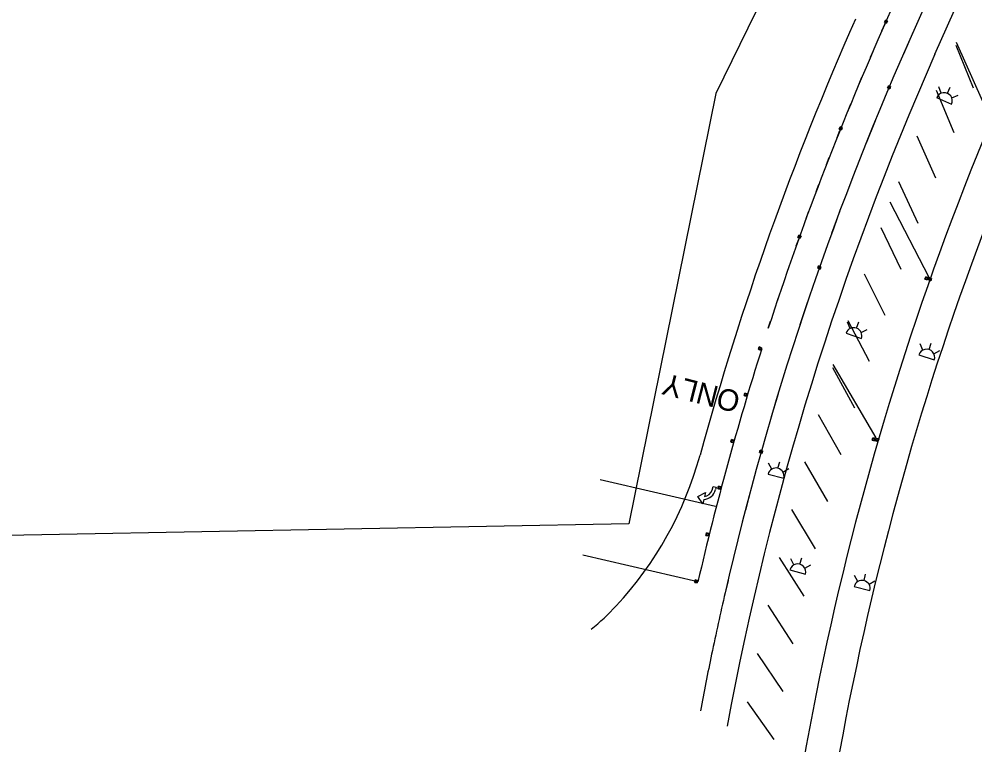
# Model space of a CAD drawing. Extents: x 2471014 to 2497726, y 6959577 to 6980268.
# Drawn here: x 2487942.2 to 2488337.8, y 6964058.7 to 6964359.1 of the extents above; entities that cross this region are included whole.
import ezdxf

# ---------------------------------------------------------------- set-up
doc = ezdxf.new("R2010")
doc.units = 0
for name, color, linetype in [('1', 7, 'Continuous'), ('13', 7, 'Continuous'), ('18', 7, 'Continuous'), ('23', 7, 'Continuous'), ('25', 7, 'Continuous'), ('C-ANNO-NOTE', 7, 'Continuous'), ('G-GRID-MAJR', 7, 'Continuous'), ('Level 30', 7, 'Continuous'), ('p_structure fence', 7, 'Continuous'), ('p_structure wall', 7, 'Continuous'), ('PMK_Del_D-SY_SZ_TYC_CTB', 7, 'Continuous'), ('PMK_Pav_Marker_TY I C', 7, 'Continuous'), ('S-BRDG-DECK', 7, 'Continuous'), ('V7_50', 7, 'Continuous')]:
    doc.layers.add(name, color=color, linetype=linetype)

msp = doc.modelspace()

# ---------------------------------------------------------------- linework, layer by layer
at = {"layer": '1'}
for p, q in [((2488312.25, 6964353.78), (2488308.21, 6964344.63)), ((2488296.51, 6964317.01), (2488292.76, 6964307.74)), ((2488281.93, 6964279.76), (2488278.47, 6964270.38)), ((2488268.54, 6964242.07), (2488265.38, 6964232.58)), ((2488256.35, 6964203.98), (2488253.49, 6964194.39)), ((2488245.37, 6964165.51), (2488242.82, 6964155.85)), ((2488235.62, 6964126.72), (2488234.43, 6964121.64))]:
    msp.add_line(p, q, dxfattribs=at)
at = {"layer": '13'}
msp.add_line((2488321.27, 6964344.52), (2488442.52, 6964618.47), dxfattribs=at)
for centre, radius, start, end in [((2489466.16, 6963837.82), 1252, 156.12666, 169.47895), ((2489494.86, 6963836.39), 1232.74, 155.64615, 177.1468)]:
    msp.add_arc(centre, radius, start, end, dxfattribs=at)
at = {"layer": '18'}
for centre, radius, start, end in [((2489466.16, 6963837.82), 1288, 156.12666, 164.66113), ((2489494.86, 6963836.39), 1246.74, 155.64615, 177.1468), ((2490212.3, 6963600.12), 1910, 158.95644, 170.95139), ((2488079.38, 6964218.21), 150, 317.1511, 344.6611), ((2489466.16, 6963837.82), 1264, 167.02427, 168.20604), ((2488116.77, 6964183.53), 99, 308.9318, 317.1511), ((2489436.79, 6963843.95), 1234, 168.20604, 169.31709)]:
    msp.add_arc(centre, radius, start, end, dxfattribs=at)
at = {"layer": '23'}
for p, q in [((2488301.61, 6964330.59), (2488302, 6964331.52)), ((2488301.83, 6964330.68), (2488301.61, 6964330.59)), ((2488301.61, 6964330.59), (2488302.54, 6964330.2)), ((2488302.33, 6964330.47), (2488301.83, 6964330.68)), ((2488302.69, 6964331.23), (2488302, 6964331.52)), ((2488302, 6964331.52), (2488302.1, 6964331.3)), ((2488302.1, 6964331.3), (2488302.72, 6964331.04)), ((2488302.46, 6964330.41), (2488302.33, 6964330.47)), ((2488302.54, 6964330.2), (2488302.46, 6964330.41)), ((2488302.93, 6964331.13), (2488302.54, 6964330.2)), ((2488302.93, 6964331.13), (2488302.69, 6964331.23)), ((2488302.72, 6964331.04), (2488302.93, 6964331.13)), ((2488272.77, 6964255.95), (2488273.11, 6964256.9)), ((2488272.99, 6964256.05), (2488272.77, 6964255.95)), ((2488272.77, 6964255.95), (2488273.73, 6964255.61)), ((2488273.5, 6964255.87), (2488272.99, 6964256.05)), ((2488273.81, 6964256.66), (2488273.11, 6964256.9)), ((2488273.11, 6964256.9), (2488273.22, 6964256.69)), ((2488273.22, 6964256.69), (2488273.86, 6964256.46)), ((2488273.63, 6964255.82), (2488273.5, 6964255.87)), ((2488273.73, 6964255.61), (2488273.63, 6964255.82)), ((2488274.06, 6964256.57), (2488273.73, 6964255.61)), ((2488274.06, 6964256.57), (2488273.81, 6964256.66)), ((2488273.86, 6964256.46), (2488274.06, 6964256.57)), ((2488317.08, 6964251.48), (2488317.42, 6964252.43)), ((2488317.3, 6964251.58), (2488317.08, 6964251.48)), ((2488317.08, 6964251.48), (2488318.03, 6964251.13)), ((2488317.81, 6964251.4), (2488317.3, 6964251.58)), ((2488318.12, 6964252.18), (2488317.42, 6964252.43)), ((2488317.42, 6964252.43), (2488317.53, 6964252.21)), ((2488317.53, 6964252.21), (2488318.17, 6964251.98)), ((2488317.94, 6964251.35), (2488317.81, 6964251.4)), ((2488318.03, 6964251.13), (2488317.94, 6964251.35)), ((2488318.37, 6964252.09), (2488318.03, 6964251.13)), ((2488318.37, 6964252.09), (2488318.12, 6964252.18)), ((2488318.17, 6964251.98), (2488318.37, 6964252.09)), ((2488318.55, 6964251.14), (2488318.9, 6964252.09)), ((2488318.78, 6964251.24), (2488318.55, 6964251.14)), ((2488318.55, 6964251.14), (2488319.5, 6964250.8)), ((2488319.28, 6964251.06), (2488318.78, 6964251.24)), ((2488319.59, 6964251.84), (2488318.9, 6964252.09)), ((2488318.9, 6964252.09), (2488319, 6964251.88)), ((2488319, 6964251.88), (2488319.64, 6964251.65)), ((2488319.41, 6964251.01), (2488319.28, 6964251.06)), ((2488319.5, 6964250.8), (2488319.41, 6964251.01)), ((2488319.85, 6964251.75), (2488319.5, 6964250.8)), ((2488319.85, 6964251.75), (2488319.59, 6964251.84)), ((2488319.64, 6964251.65), (2488319.85, 6964251.75)), ((2488248.18, 6964222.41), (2488248.49, 6964223.38)), ((2488248.39, 6964222.52), (2488248.18, 6964222.41)), ((2488248.18, 6964222.41), (2488248.44, 6964222.33)), ((2488249.03, 6964222.31), (2488248.39, 6964222.52)), ((2488248.44, 6964222.33), (2488249.15, 6964222.1)), ((2488249.46, 6964223.07), (2488248.49, 6964223.38)), ((2488248.49, 6964223.38), (2488248.59, 6964223.16)), ((2488248.59, 6964223.16), (2488248.73, 6964223.12)), ((2488248.73, 6964223.12), (2488249.24, 6964222.96)), ((2488249.15, 6964222.1), (2488249.03, 6964222.31)), ((2488249.46, 6964223.07), (2488249.15, 6964222.1)), ((2488249.24, 6964222.96), (2488249.46, 6964223.07)), ((2488242.31, 6964203.28), (2488242.6, 6964204.25)), ((2488242.51, 6964203.4), (2488242.31, 6964203.28)), ((2488242.31, 6964203.28), (2488242.57, 6964203.2)), ((2488243.16, 6964203.2), (2488242.51, 6964203.4)), ((2488242.57, 6964203.2), (2488243.28, 6964202.99)), ((2488243.57, 6964203.96), (2488242.6, 6964204.25)), ((2488242.6, 6964204.25), (2488242.7, 6964204.05)), ((2488242.7, 6964204.05), (2488242.84, 6964204)), ((2488242.84, 6964204), (2488243.35, 6964203.85)), ((2488243.28, 6964202.99), (2488243.16, 6964203.2)), ((2488243.57, 6964203.96), (2488243.28, 6964202.99)), ((2488243.35, 6964203.85), (2488243.57, 6964203.96)), ((2488295.23, 6964184.85), (2488295.52, 6964185.82)), ((2488296.23, 6964185.61), (2488295.52, 6964185.82)), ((2488295.52, 6964185.82), (2488295.64, 6964185.61)), ((2488236.74, 6964184.07), (2488237.01, 6964185.04)), ((2488236.93, 6964184.18), (2488236.74, 6964184.07)), ((2488236.74, 6964184.07), (2488236.99, 6964183.99)), ((2488237.59, 6964184), (2488236.93, 6964184.18)), ((2488236.99, 6964183.99), (2488237.71, 6964183.79)), ((2488237.99, 6964184.77), (2488237.01, 6964185.04)), ((2488237.01, 6964185.04), (2488237.12, 6964184.84)), ((2488237.12, 6964184.84), (2488237.25, 6964184.8)), ((2488237.25, 6964184.8), (2488237.77, 6964184.65)), ((2488237.71, 6964183.79), (2488237.59, 6964184)), ((2488237.99, 6964184.77), (2488237.71, 6964183.79)), ((2488237.77, 6964184.65), (2488237.99, 6964184.77)), ((2488295.45, 6964184.96), (2488295.23, 6964184.85)), ((2488295.23, 6964184.85), (2488296.2, 6964184.56)), ((2488295.96, 6964184.81), (2488295.45, 6964184.96)), ((2488295.64, 6964185.61), (2488296.29, 6964185.42)), ((2488296.1, 6964184.77), (2488295.96, 6964184.81)), ((2488296.2, 6964184.56), (2488296.1, 6964184.77)), ((2488296.49, 6964185.53), (2488296.2, 6964184.56)), ((2488296.49, 6964185.53), (2488296.23, 6964185.61)), ((2488296.29, 6964185.42), (2488296.49, 6964185.53)), ((2488296.71, 6964184.56), (2488297, 6964185.53)), ((2488296.93, 6964184.67), (2488296.71, 6964184.56)), ((2488296.71, 6964184.56), (2488297.68, 6964184.27)), ((2488297.44, 6964184.52), (2488296.93, 6964184.67)), ((2488297.71, 6964185.32), (2488297, 6964185.53)), ((2488297, 6964185.53), (2488297.12, 6964185.32)), ((2488297.12, 6964185.32), (2488297.77, 6964185.13)), ((2488297.58, 6964184.48), (2488297.44, 6964184.52)), ((2488297.68, 6964184.27), (2488297.58, 6964184.48)), ((2488297.97, 6964185.24), (2488297.68, 6964184.27)), ((2488297.97, 6964185.24), (2488297.71, 6964185.32)), ((2488297.77, 6964185.13), (2488297.97, 6964185.24)), ((2488248.71, 6964179.63), (2488248.99, 6964180.61)), ((2488248.93, 6964179.75), (2488248.71, 6964179.63)), ((2488248.71, 6964179.63), (2488249.69, 6964179.36)), ((2488249.44, 6964179.6), (2488248.93, 6964179.75)), ((2488249.7, 6964180.4), (2488248.99, 6964180.61)), ((2488248.99, 6964180.61), (2488249.11, 6964180.4)), ((2488249.11, 6964180.4), (2488249.76, 6964180.21)), ((2488249.58, 6964179.56), (2488249.44, 6964179.6)), ((2488249.69, 6964179.36), (2488249.58, 6964179.56)), ((2488249.96, 6964180.33), (2488249.69, 6964179.36)), ((2488249.96, 6964180.33), (2488249.7, 6964180.4)), ((2488249.76, 6964180.21), (2488249.96, 6964180.33)), ((2488231.46, 6964164.77), (2488231.72, 6964165.75)), ((2488231.66, 6964164.89), (2488231.46, 6964164.77)), ((2488231.46, 6964164.77), (2488231.72, 6964164.7)), ((2488232.31, 6964164.71), (2488231.66, 6964164.89)), ((2488232.7, 6964165.49), (2488231.72, 6964165.75)), ((2488231.72, 6964165.75), (2488231.83, 6964165.54)), ((2488231.72, 6964164.7), (2488232.44, 6964164.51)), ((2488231.83, 6964165.54), (2488231.97, 6964165.51)), ((2488231.97, 6964165.51), (2488232.49, 6964165.37)), ((2488232.44, 6964164.51), (2488232.31, 6964164.71)), ((2488232.7, 6964165.49), (2488232.44, 6964164.51)), ((2488232.49, 6964165.37), (2488232.7, 6964165.49)), ((2488226.49, 6964145.39), (2488226.74, 6964146.37)), ((2488227.72, 6964146.12), (2488226.74, 6964146.37)), ((2488226.74, 6964146.37), (2488226.85, 6964146.17)), ((2488226.85, 6964146.17), (2488226.99, 6964146.13)), ((2488226.69, 6964145.51), (2488226.49, 6964145.39)), ((2488226.49, 6964145.39), (2488226.75, 6964145.32)), ((2488227.35, 6964145.35), (2488226.69, 6964145.51)), ((2488226.75, 6964145.32), (2488227.48, 6964145.14)), ((2488226.99, 6964146.13), (2488227.51, 6964146)), ((2488227.48, 6964145.14), (2488227.35, 6964145.35)), ((2488227.72, 6964146.12), (2488227.48, 6964145.14)), ((2488227.51, 6964146), (2488227.72, 6964146.12)), ((2488221.83, 6964125.93), (2488222.06, 6964126.92)), ((2488223.04, 6964126.69), (2488222.06, 6964126.92)), ((2488222.06, 6964126.92), (2488222.17, 6964126.72)), ((2488222.17, 6964126.72), (2488222.31, 6964126.68)), ((2488222.31, 6964126.68), (2488222.83, 6964126.56)), ((2488223.04, 6964126.69), (2488222.81, 6964125.7)), ((2488222.83, 6964126.56), (2488223.04, 6964126.69)), ((2488222.02, 6964126.06), (2488221.83, 6964125.93)), ((2488221.83, 6964125.93), (2488222.09, 6964125.87)), ((2488222.68, 6964125.9), (2488222.02, 6964126.06)), ((2488222.09, 6964125.87), (2488222.81, 6964125.7)), ((2488222.81, 6964125.7), (2488222.68, 6964125.9))]:
    msp.add_line(p, q, dxfattribs=at)
for points in [[(2488302.72, 6964331.04), (2488302.46, 6964330.41), (2488301.83, 6964330.68), (2488302.1, 6964331.3)], [(2488273.86, 6964256.46), (2488273.63, 6964255.82), (2488272.99, 6964256.05), (2488273.22, 6964256.69)], [(2488318.17, 6964251.98), (2488317.94, 6964251.35), (2488317.3, 6964251.58), (2488317.53, 6964252.21)], [(2488319.64, 6964251.65), (2488319.41, 6964251.01), (2488318.78, 6964251.24), (2488319, 6964251.88)], [(2488248.39, 6964222.52), (2488248.59, 6964223.16), (2488249.24, 6964222.96), (2488249.03, 6964222.31)], [(2488242.51, 6964203.4), (2488242.7, 6964204.05), (2488243.35, 6964203.85), (2488243.16, 6964203.2)], [(2488236.93, 6964184.18), (2488237.12, 6964184.84), (2488237.77, 6964184.65), (2488237.59, 6964184)], [(2488296.29, 6964185.42), (2488296.1, 6964184.77), (2488295.45, 6964184.96), (2488295.64, 6964185.61)], [(2488297.77, 6964185.13), (2488297.58, 6964184.48), (2488296.93, 6964184.67), (2488297.12, 6964185.32)], [(2488249.76, 6964180.21), (2488249.58, 6964179.56), (2488248.93, 6964179.75), (2488249.11, 6964180.4)], [(2488231.66, 6964164.89), (2488231.83, 6964165.54), (2488232.49, 6964165.37), (2488232.31, 6964164.71)], [(2488226.69, 6964145.51), (2488226.85, 6964146.17), (2488227.51, 6964146), (2488227.35, 6964145.35)], [(2488222.02, 6964126.06), (2488222.17, 6964126.72), (2488222.83, 6964126.56), (2488222.68, 6964125.9)]]:
    msp.add_lwpolyline(points, close=True, dxfattribs=at)
at = {"layer": '25'}
for p, q in [((2488299.39, 6964354.39), (2488300.61, 6964357.13)), ((2488294.59, 6964343.39), (2488295.78, 6964346.15)), ((2488289.88, 6964332.35), (2488291.05, 6964335.12)), ((2488285.29, 6964321.27), (2488286.43, 6964324.04)), ((2488280.79, 6964310.14), (2488281.91, 6964312.93)), ((2488276.4, 6964298.97), (2488277.49, 6964301.77)), ((2488272.12, 6964287.76), (2488273.18, 6964290.57)), ((2488267.94, 6964276.52), (2488268.97, 6964279.33)), ((2488263.87, 6964265.23), (2488264.88, 6964268.05)), ((2488259.9, 6964253.9), (2488260.88, 6964256.74)), ((2488256.04, 6964242.54), (2488257, 6964245.38)), ((2488252.29, 6964231.14), (2488253.22, 6964233.99))]:
    msp.add_line(p, q, dxfattribs=at)
msp.add_arc((2489466.16, 6963837.82), 1276, 162.45055, 166.94082, dxfattribs=at)
at = {"layer": 'C-ANNO-NOTE'}
for p, q in [((2488299.33, 6964354.24), (2488420.57, 6964628.19)), ((2488431.55, 6964623.33), (2488310.3, 6964349.38)), ((2488230.39, 6964157.31), (2488182.7, 6964168.38)), ((2488223.16, 6964126.14), (2488175.47, 6964137.2))]:
    msp.add_line(p, q, dxfattribs=at)
for radius, end in [(1276, 162.04643), (1264, 167.02427)]:
    msp.add_arc((2489466.16, 6963837.82), radius, 156.12666, end, dxfattribs=at)
at = {"layer": 'G-GRID-MAJR'}
for p, q in [((2488330.07, 6964349.51), (2488344.35, 6964317.35)), ((2488302.6, 6964283.52), (2488318.7, 6964252.23)), ((2488278.95, 6964216.06), (2488296.82, 6964185.74))]:
    msp.add_line(p, q, dxfattribs=at)
at = {"layer": 'Level 30'}
for p, q in [((2488323.83, 6964328.42), (2488322.91, 6964331.08)), ((2488326.41, 6964328.37), (2488327.54, 6964330.95)), ((2488321.97, 6964326.63), (2488328.15, 6964323.93)), ((2488328.2, 6964326.51), (2488330.81, 6964327.57)), ((2488286.22, 6964231.03), (2488285.13, 6964233.62)), ((2488288.8, 6964231.15), (2488289.76, 6964233.79)), ((2488290.71, 6964229.41), (2488293.24, 6964230.64)), ((2488284.48, 6964229.12), (2488290.83, 6964226.83)), ((2488262.82, 6964133.17), (2488261.56, 6964135.69)), ((2488265.39, 6964133.45), (2488266.18, 6964136.15)), ((2488261.2, 6964131.16), (2488267.68, 6964129.26)), ((2488267.4, 6964131.83), (2488269.85, 6964133.21))]:
    msp.add_line(p, q, dxfattribs=at)
for centre, start, end in [((2488325.06, 6964325.28), 336.3512, 156.3512), ((2488287.66, 6964227.98), 340.1091, 160.1091), ((2488264.44, 6964130.21), 343.6986, 163.6986)]:
    msp.add_arc(centre, 3.37, start, end, dxfattribs=at)
at = {"layer": 'p_structure wall'}
for p, q in [((2488223.19, 6964161.45), (2488226.28, 6964163.07)), ((2488226.28, 6964163.07), (2488225.88, 6964161.45)), ((2488229.24, 6964164.62), (2488229.47, 6964165.58)), ((2488229.47, 6964165.58), (2488230.67, 6964165.29)), ((2488230.67, 6964165.29), (2488230.43, 6964164.33)), ((2488225.26, 6964158.5), (2488223.19, 6964161.45)), ((2488225.67, 6964160.17), (2488225.26, 6964158.5))]:
    msp.add_line(p, q, dxfattribs=at)
for radius, start, end in [(5.49, 275.9754, 346.2648), (4.26, 280.651, 338.3936), (4.26, 338.3936, 340.641), (4.26, 340.641, 346.2238)]:
    msp.add_arc((2488225.09, 6964165.64), radius, start, end, dxfattribs=at)
at = {"layer": 'PMK_Del_D-SY_SZ_TYC_CTB'}
for p, q in [((2488316.28, 6964222.11), (2488315.13, 6964224.68)), ((2488318.86, 6964222.29), (2488319.75, 6964224.96)), ((2488320.8, 6964220.59), (2488323.3, 6964221.88)), ((2488314.58, 6964220.17), (2488320.98, 6964218.01)), ((2488253.74, 6964172.83), (2488252.42, 6964175.31)), ((2488256.3, 6964173.17), (2488257.02, 6964175.89)), ((2488252.18, 6964170.77), (2488258.7, 6964169.05)), ((2488258.36, 6964171.61), (2488260.77, 6964173.06)), ((2488289.35, 6964126.27), (2488287.98, 6964128.73)), ((2488291.9, 6964126.66), (2488292.57, 6964129.39)), ((2488293.98, 6964125.13), (2488296.37, 6964126.62)), ((2488287.82, 6964124.19), (2488294.37, 6964122.57))]:
    msp.add_line(p, q, dxfattribs=at)
for centre, start, end in [((2488317.78, 6964219.09), 341.3984, 161.3984), ((2488255.44, 6964169.91), 345.2245, 165.2245), ((2488291.09, 6964123.38), 346.1493, 166.1493)]:
    msp.add_arc(centre, 3.37, start, end, dxfattribs=at)
at = {"layer": 'PMK_Pav_Marker_TY I C'}
for p, q in [((2488300.34, 6964357.79), (2488300.75, 6964358.72)), ((2488300.57, 6964357.87), (2488300.34, 6964357.79)), ((2488300.34, 6964357.79), (2488301.26, 6964357.38)), ((2488301.06, 6964357.66), (2488300.57, 6964357.87)), ((2488301.43, 6964358.42), (2488300.75, 6964358.72)), ((2488300.75, 6964358.72), (2488300.84, 6964358.49)), ((2488300.84, 6964358.49), (2488301.46, 6964358.22)), ((2488301.18, 6964357.6), (2488301.06, 6964357.66)), ((2488301.26, 6964357.38), (2488301.18, 6964357.6)), ((2488301.67, 6964358.31), (2488301.26, 6964357.38)), ((2488301.67, 6964358.31), (2488301.43, 6964358.42)), ((2488301.46, 6964358.22), (2488301.67, 6964358.31)), ((2488281.61, 6964313.58), (2488281.99, 6964314.52)), ((2488281.84, 6964313.67), (2488281.61, 6964313.58)), ((2488281.61, 6964313.58), (2488282.55, 6964313.2)), ((2488282.33, 6964313.47), (2488281.84, 6964313.67)), ((2488282.68, 6964314.24), (2488281.99, 6964314.52)), ((2488281.99, 6964314.52), (2488282.09, 6964314.3)), ((2488282.09, 6964314.3), (2488282.72, 6964314.04)), ((2488282.47, 6964313.42), (2488282.33, 6964313.47)), ((2488282.55, 6964313.2), (2488282.47, 6964313.42)), ((2488282.93, 6964314.14), (2488282.55, 6964313.2)), ((2488282.93, 6964314.14), (2488282.68, 6964314.24)), ((2488282.72, 6964314.04), (2488282.93, 6964314.14)), ((2488264.56, 6964268.69), (2488264.9, 6964269.65)), ((2488264.78, 6964268.79), (2488264.56, 6964268.69)), ((2488265.28, 6964268.61), (2488264.78, 6964268.79)), ((2488265.6, 6964269.39), (2488264.9, 6964269.65)), ((2488264.9, 6964269.65), (2488265.01, 6964269.43)), ((2488265.01, 6964269.43), (2488265.64, 6964269.2)), ((2488265.85, 6964269.3), (2488265.51, 6964268.35)), ((2488265.85, 6964269.3), (2488265.6, 6964269.39)), ((2488265.64, 6964269.2), (2488265.85, 6964269.3)), ((2488264.56, 6964268.69), (2488265.51, 6964268.35)), ((2488265.42, 6964268.56), (2488265.28, 6964268.61)), ((2488265.51, 6964268.35), (2488265.42, 6964268.56))]:
    msp.add_line(p, q, dxfattribs=at)
for points in [[(2488301.46, 6964358.22), (2488301.18, 6964357.6), (2488300.57, 6964357.87), (2488300.84, 6964358.49)], [(2488282.72, 6964314.04), (2488282.47, 6964313.42), (2488281.84, 6964313.67), (2488282.09, 6964314.3)], [(2488265.64, 6964269.2), (2488265.42, 6964268.56), (2488264.78, 6964268.79), (2488265.01, 6964269.43)]]:
    msp.add_lwpolyline(points, close=True, dxfattribs=at)
at = {"layer": 'S-BRDG-DECK'}
for p, q in [((2488329.92, 6964348.36), (2488337.04, 6964330.7)), ((2488321.7, 6964329.66), (2488329.12, 6964312.12)), ((2488313.79, 6964310.84), (2488321.49, 6964293.42)), ((2488306.19, 6964291.88), (2488314.18, 6964274.6)), ((2488298.91, 6964272.81), (2488307.17, 6964255.65)), ((2488291.93, 6964253.61), (2488300.48, 6964236.6)), ((2488285.27, 6964234.31), (2488294.1, 6964217.44)), ((2488278.93, 6964214.9), (2488288.03, 6964198.17)), ((2488272.91, 6964195.39), (2488282.29, 6964178.81)), ((2488267.21, 6964175.78), (2488276.85, 6964159.36)), ((2488261.83, 6964156.08), (2488271.74, 6964139.82)), ((2488256.78, 6964136.29), (2488266.95, 6964120.2)), ((2488252.05, 6964116.43), (2488262.49, 6964100.5)), ((2488247.64, 6964096.49), (2488258.34, 6964080.74)), ((2488243.57, 6964076.48), (2488254.52, 6964060.9))]:
    msp.add_line(p, q, dxfattribs=at)
at = {"layer": 'V7_50'}
msp.add_lwpolyline([(2488749.92, 6965620.02), (2488565.91, 6965187.54), (2488339.44, 6964725), (2488406.92, 6964688.38), (2488230.6, 6964328.26), (2488194.55, 6964150.2), (2487723.2, 6964141.3), (2487751.76, 6964063.99), (2487755.8, 6964057.06), (2487772.72, 6964031.64), (2487802.7, 6963984.42), (2487818.64, 6963994.63), (2487839.08, 6964022.95), (2487853.92, 6964044.17), (2487900.89, 6964040.04), (2487966.86, 6964027.87), (2488031.89, 6964011.9), (2488110.54, 6963990.9), (2488167.29, 6963971.94), (2488185.02, 6963947.44), (2488182.31, 6963911.72), (2488180.79, 6963878.32), (2488180.28, 6963834.39), (2488180.96, 6963804.18)], dxfattribs=at)

# ---------------------------------------------------------------- texts
at = {"layer": 'p_structure fence'}
msp.add_text('ONLY', height=8.898, rotation=165.7644, dxfattribs=at).set_placement((2488241.29, 6964204.6))

doc.saveas('drawing.dxf')
